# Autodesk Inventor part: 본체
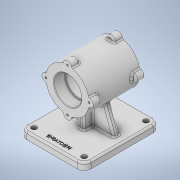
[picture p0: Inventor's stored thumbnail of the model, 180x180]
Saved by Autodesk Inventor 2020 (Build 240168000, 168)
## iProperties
Created: 2022-11
Part Number: 본체
Material: 일반
Document SubType Name: Modeling
Designer: owner
Density: 1 g/cm^3
Appearance: 기본값
Author: owner
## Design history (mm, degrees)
sketch "스케치1"
  geometry: L1 (65, -55)-(-65, -55); L2 (-65, -55)-(-65, 55); L3 (-65, 55)-(65, 55); L4 (65, 55)-(65, -55); L5 (65, -55)-(-65, 55); L6 (-65, -55)-(65, 55); 1 further point
  constraints: 12 end point, 2 midpoint, 2 parallel, 1 horizontal, 1 perpendicular
  dimensions: "d0" = 130 distance of L2.end L3.end; "d1" = 110 distance of L1.end L2.end
extrude "돌출1" new body sketch "스케치1" distance "d2" = 12; taper "d3" = 0 deg
node "작업 평면7"
sketch "스케치5"
  geometry: L1 (0, 0)-(110, 0) reference; C1 r 37 at (55, 82); 2 further points
  constraints: 1 centre point, 1 midpoint, 1 vertical alignment
  dimensions: "d11" = 74 diameter of C1; "d12" = 82 distance from line of L1 C1.centre
extrude "돌출2" join sketch "스케치5" stored distance "d13" = 87; taper "d14" = 0 deg
sketch "스케치7"
  geometry: C1 r 37 at (0, 0) reference; 2 further points
  constraints: 1 coincident
hole "구멍1" sketch "스케치7" at (0, 0) diameter "d17" = 42; stored, may be unused: countersink angle "d21" = 90 deg, drill point angle "d23" = 0 deg; dims "d18" = 12, "d19" = 47, "d20" = 19, "d22" = 43.5
sketch "스케치8"
  geometry: C1 r 37 at (0, 0) reference; A1 r 37 centre (0, 0) between (0, 37) and (-6.969, 36.338) reference; A2 r 7 centre (0, 37) between (6.969, 36.338) and (-6.969, 36.338); 3 further points
  constraints: 5 point on circle, 1 centre point, 1 vertical alignment
  dimensions: "d24" = 14 diameter of A2
extrude "돌출3" join sketch "스케치8" distance "d25" = 14; taper "d26" = 0 deg
sketch "스케치9"
  geometry: A1 r 7 centre (55, 119) between (61.969, 118.338) and (48.031, 118.338) reference; 2 further points
  constraints: 1 coincident
hole "구멍2" sketch "스케치9" at (55, 119) diameter "d27" = 3.242; stored, may be unused: countersink angle "d31" = 90 deg, drill point angle "d33" = 118 deg; dims "d28" = 8, "d29" = 47, "d30" = 19, "d32" = 10
sketch "스케치10"
  geometry: L1 (0, 12)-(110, 12) reference; L2 (96, 12)-(80.336, 55.036); L3 (110, 0)-(110, 12) reference; L4 (55, 45)-(55, 12); A1 r 37 centre (55, 82) between (61.969, 45.662) and (91.338, 75.031) reference; A2 r 37 centre (55, 82) between (91.338, 88.969) and (61.969, 118.338) reference; A3 r 37 centre (55, 82) between (61.969, 118.338) and (48.031, 118.338) reference; A4 r 37 centre (55, 82) between (48.031, 118.338) and (18.662, 88.969) reference; A5 r 37 centre (55, 82) between (18.662, 88.969) and (18.662, 75.031) reference; A6 r 37 centre (55, 82) between (18.662, 75.031) and (48.031, 45.662) reference; A7 r 37 centre (55, 82) between (48.031, 45.662) and (61.969, 45.662) reference; A8 r 37 centre (55, 82) between (61.969, 45.662) and (91.338, 75.031) reference; A9 r 37 centre (55, 82) between (91.338, 75.031) and (91.338, 88.969) reference; A10 r 37 centre (55, 82) between (91.338, 75.031) and (91.338, 88.969) reference; A11 r 37 centre (55, 82) between (61.969, 45.662) and (91.338, 75.031) reference; A12 r 37 centre (55, 82) between (48.031, 45.662) and (61.969, 45.662) reference; A13 r 37 centre (55, 82) between (18.662, 75.031) and (48.031, 45.662) reference; A14 r 37 centre (55, 82) between (18.662, 88.969) and (18.662, 75.031) reference; A15 r 37 centre (55, 82) between (48.031, 118.338) and (18.662, 88.969) reference; A16 r 37 centre (55, 82) between (61.969, 118.338) and (48.031, 118.338) reference; A17 r 37 centre (55, 82) between (91.338, 88.969) and (61.969, 118.338) reference; 4 further points
  constraints: 4 end point, 2 point on circle, 1 midpoint, 1 point on line, 2 other
  dimensions: "d37" = 14 distance from line of L3 L2.start; "d38" = 110 deg angle of L1 L2
extrude "돌출4" join sketch "스케치10" stored distance "d39" = 10; taper "d40" = 0 deg
node "작업 평면9"
sketch "스케치18"
  geometry: L1 (99.5, 45)-(40.5, 45) reference; L2 (75, 55.036)-(75, 12) reference; L3 (0, 12)-(130, 12) reference; L4 (90, 12)-(90, 45); L5 (70, -25.2)-(70, 151.2) reference; 1 further point
  constraints: 2 end point, 2 point on line, 1 perpendicular
  dimensions: "d47" = 20 distance between parallel lines of L4 L5
feature "리브1" sketch "스케치18" dims "d48" = 1, "d49" = 10, "d50" = 0, "d51" = 0, "d52" = 1, "d53" = 1
sketch "스케치20"
  geometry: L1 (10, -41)-(0, -41) reference; 3 further points
  constraints: 2 midpoint
fillet "모깎기3" dims "d61" = 12
sketch "스케치21"
  geometry: A1 r 12 centre (-53, -43) between (-65, -43) and (-53, -55) reference; 2 further points
  constraints: 1 coincident
hole "구멍3" sketch "스케치21" at (-53, -43) diameter "d62" = 9; stored, may be unused: countersink angle "d66" = 90 deg, drill point angle "d68" = 0 deg; dims "d63" = 8, "d64" = 47, "d65" = 19, "d67" = 10
fillet "모깎기4" dims "d69" = 3
fillet "모깎기5" dims "d70" = 3
fillet "모깎기6" dims "d71" = 3
fillet "모깎기7" dims "d72" = 3
fillet "모깎기8" dims "d73" = 3
fillet "모깎기9" dims "d74" = 3
fillet "모깎기10" dims "d75" = 3
fillet "모깎기11" dims "d76" = 3
chamfer "모따기1" distance "d77" = 1; stored, may be unused: second distance "d78" = 2, angle "d79" = 45 deg
chamfer "모따기2" distance "d80" = 1; stored, may be unused: second distance "d81" = 2, angle "d82" = 45 deg
fillet "모깎기13" dims "d84" = 1
sketch "스케치23"
  geometry: L1 (5, -77)-(5, 77) reference; 2 further points
  constraints: 1 horizontal alignment, 1 other
  dimensions: "d85" = 58 distance from line of L1 point (-53, 0)
feature "엠보싱1" sketch "스케치23" dims "d19" = 47, "d86" = 0.5, "d87" = 0
node "솔리드1"
mirror "미러1"
pattern_circular "원형 패턴1" dims angle "d35" = 360 deg
mirror "미러2"
mirror "미러3"
mirror "미러4"
mirror "미러5"
mirror "미러6"
node "투영된 루프1"
feature "A9D066F2-1C7D-4E18-AEED-F7BC21143FA4" dims "d17" = 42, "d18" = 12, "d19" = 47, "d20" = 19, "d21" = 90 deg, "d22" = 43.5, "d23" = 0
